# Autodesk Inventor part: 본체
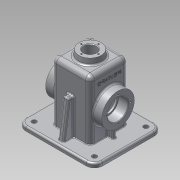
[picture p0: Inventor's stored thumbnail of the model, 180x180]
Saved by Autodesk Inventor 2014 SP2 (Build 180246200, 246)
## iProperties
Created: 2016-08
Part Number: 본체
Material: 알루미늄 6061
Document SubType Name: Modeling
Designer: user
Density: 2.71 g/cm^3
Appearance: 알루미늄 - 평지
Mass: 796.016 g
Surface Area: 911.319 cm^2
Volume: 293.733 cm^3
Author: user
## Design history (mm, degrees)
sketch "스케치1"
  geometry: L1 (-32.5, -32.5)-(32.5, -32.5); L2 (32.5, -32.5)-(32.5, 32.5); L3 (32.5, 32.5)-(-32.5, 32.5); L4 (-32.5, 32.5)-(-32.5, -32.5); L5 (-32.5, -32.5)-(32.5, 32.5); L6 (32.5, -32.5)-(-32.5, 32.5); 1 further point
  constraints: 12 end point, 2 midpoint, 2 parallel, 1 horizontal, 1 perpendicular
  dimensions: "d0" = 65 distance of L3.end L2.end; "d1" = 65 distance of L2.end L1.end
extrude "돌출1" new body sketch "스케치1" stored distance "d2" = 100; taper "d3" = 0 deg
sketch "스케치2"
  geometry: L1 (65, 57.5)-(-65, 57.5); L2 (-65, 57.5)-(-65, -57.5); L3 (-65, -57.5)-(65, -57.5); L4 (65, -57.5)-(65, 57.5); L5 (65, 57.5)-(-65, -57.5); L6 (-65, 57.5)-(65, -57.5); 1 further point
  constraints: 12 end point, 2 midpoint, 2 parallel, 1 horizontal, 1 perpendicular
  dimensions: "d4" = 130 distance of L3.end L2.end; "d5" = 115 distance of L2.end L1.end
extrude "돌출2" join sketch "스케치2" distance "d6" = 7; taper "d7" = 0 deg
sketch "스케치3"
  geometry: L1 (-65, -57.5)-(65, -57.5) reference; L2 (65, -57.5)-(65, 57.5) reference; L3 (65, 57.5)-(-65, 57.5) reference; L4 (-65, 57.5)-(-65, -57.5) reference; L5 (60, -52.5)-(-60, -52.5); L6 (-60, -52.5)-(-60, 52.5); L7 (-60, 52.5)-(60, 52.5); L8 (60, 52.5)-(60, -52.5); 1 further point
  constraints: 8 end point, 3 other
  dimensions: "d8" = 5 distance between parallel lines of L1 L5
extrude "돌출3" join sketch "스케치3" distance "d9" = 3; taper "d10" = 0 deg
fillet "모깎기1" dims "d11" = 8
fillet "모깎기2" dims "d12" = 8
sketch "스케치4"
  geometry: L1 (10, 77)-(10, -28) reference; L2 (-92, -8)-(0, -8) reference; C1 r 27.5 at (-45, 24.5); 1 further point
  constraints: 1 centre point
  dimensions: "d13" = 55 distance from line of L1 C1.centre; "d14" = 55 diameter of C1; "d15" = 32.5 distance from line of L2 C1.centre
extrude "돌출4" join sketch "스케치4" distance "d16" = 15; taper "d17" = 0 deg
sketch "스케치5"
  geometry: L1 (60, -60)-(-60, -60) reference; L2 (27.5, -60)-(27.5, 42); L3 (24.5, 45)-(-24.5, 45); L4 (-27.5, 42)-(-27.5, -60); L5 (27.5, -60)-(-27.5, -60); L6 (32.5, 7.49)-(32.5, 42) reference; L7 (-32.5, 42)-(-32.5, 7.49) reference; L8 (24.5, 50)-(-24.5, 50) reference; A1 r 3 centre (24.5, 42) between (27.5, 42) and (24.5, 45); A2 r 3 centre (-24.5, 42) between (-24.5, 45) and (-27.5, 42); 1 further point
  constraints: 8 end point, 4 perpendicular, 4 point on circle, 4 tangent, 2 centre point, 2 point on line, 1 equal radius
  dimensions: "d18" = 5 distance between parallel lines of L6 L2; "d19" = 5 distance between parallel lines of L7 L4; "d20" = 5 distance between parallel lines of L3 L8; "d21" = 3 radius of A1
extrude "돌출5" cut sketch "스케치5" stored distance "d22" = 55; taper "d23" = 0 deg
fillet "모깎기3" dims "d24" = 3
sketch "스케치7"
  geometry: L1 (32.5, 42)-(32.5, -50) reference; L2 (-57.5, -50)-(57.5, -50) reference; L3 (57.5, -50)-(57.5, -57) reference; L4 (49.5, -50)-(41.068, 10); L5 (-52.5, -60)-(52.5, -60) reference; L6 (-49.5, -50)-(-41.068, 10); L7 (-57.5, -50)-(-57.5, -57) reference; L8 (41.068, 10)-(32.5, 10); 1 further point
  constraints: 6 end point, 3 point on line, 1 perpendicular
  dimensions: "d30" = 70 distance from line of L5 L4.end; "d31" = 8 deg angle of L3 L4; "d32" = 8 distance of L2.end L4.start; "d33" = 8 deg angle of L7 L6; "d34" = 70 distance from line of L5 L6.end; "d35" = 8 distance from line of L7 L6.start
feature "리브1" sketch "스케치7" dims "d36" = 1, "d37" = 10, "d38" = 0, "d39" = 0, "d40" = 1, "d41" = 1
sketch "스케치8"
  geometry: L1 (47.5, 22.5)-(47.5, -32.5) reference; L2 (47.5, -5)-(-47.5, -5); L3 (-47.5, 22.5)-(-47.5, -32.5) reference; L4 (47.5, -5)-(47.5, 12.5); L5 (47.5, 12.5)-(30.5, 12.5); L6 (30.5, 12.5)-(30.5, 10); L7 (30.5, 10)-(-30.5, 10); L8 (-30.5, 10)-(-30.5, 12.5); L9 (-30.5, 12.5)-(-47.5, 12.5); L10 (-47.5, 12.5)-(-47.5, -5); 1 further point
  constraints: 16 end point, 5 perpendicular, 2 midpoint, 2 parallel, 2 point on line
  dimensions: "d42" = 17 distance of L4.end L5.end; "d43" = 17 distance of L8.end L9.end; "d44" = 30 diameter of L7 L2; "d45" = 35 diameter of L9 L2; "d46" = 35 diameter of L5 L2
revolve "회전1" sketch "스케치8" stored, may be unused: angle "d47" = 90 deg
sketch "스케치9"
  geometry: C1 r 27.5 at (0, 0) reference; 2 further points
  constraints: 1 horizontal alignment
  dimensions: "d48" = 21 distance of C1.centre point (-21, 0)
hole "구멍1" sketch "스케치9" at (-21, 0) diameter "d49" = 3.242; stored, may be unused: countersink angle "d53" = 90 deg, drill point angle "d55" = 118 deg; dims "d50" = 8, "d51" = 4, "d52" = 2, "d54" = 10
fillet "모깎기4" dims "d59" = 14
fillet "모깎기5" dims "d60" = 9
hole "구멍2" diameter "d63" = 8; stored, may be unused: countersink angle "d67" = 90 deg, drill point angle "d69" = 118 deg; dims "d61" = 10, "d62" = 10, "d64" = 8, "d65" = 4, "d66" = 2, "d68" = 10
hole "구멍3" diameter "d72" = 8; stored, may be unused: countersink angle "d76" = 90 deg, drill point angle "d78" = 118 deg; dims "d70" = 10, "d71" = 10, "d73" = 8, "d74" = 4, "d75" = 2, "d77" = 10
hole "구멍4" diameter "d81" = 8; stored, may be unused: countersink angle "d85" = 90 deg, drill point angle "d87" = 118 deg; dims "d79" = 10, "d80" = 10, "d82" = 8, "d83" = 4, "d84" = 2, "d86" = 10
hole "구멍5" diameter "d90" = 8; stored, may be unused: countersink angle "d94" = 90 deg, drill point angle "d96" = 118 deg; dims "d88" = 10, "d89" = 10, "d91" = 8, "d92" = 4, "d93" = 2, "d95" = 10
sketch "스케치11"
  geometry: C1 r 20 at (0, 0); 1 further point
  constraints: 1 centre point, 1 coincident
  dimensions: "d97" = 40 diameter of C1
extrude "돌출7" join sketch "스케치11" distance "d98" = 10; taper "d99" = -7 deg
hole "구멍6" diameter "d102" = 21; stored, may be unused: countersink angle "d106" = 90 deg, drill point angle "d108" = 118 deg; dims "d100" = 10, "d101" = 10, "d103" = 8, "d104" = 4, "d105" = 2, "d107" = 10
sketch "스케치12"
  geometry: A1 r 14.5 centre (0, 0) between (0, 14.5) and (0, -14.5); 3 further points
  constraints: 4 point on circle, 2 horizontal alignment, 2 vertical alignment, 1 centre point, 1 coincident
  dimensions: "d109" = 29 diameter of A1
hole "구멍7" sketch "스케치12" at (0, 14.5), (0, -14.5), (14.5, 0), (-14.5, 0) diameter "d110" = 2.459; stored, may be unused: countersink angle "d114" = 90 deg, drill point angle "d116" = 118 deg; dims "d111" = 7, "d112" = 4, "d113" = 2, "d115" = 9
node "작업 평면1"
sketch "스케치13"
  geometry: L1 (0, -8)-(92, -8) reference; L2 (-18, 5.728)-(-18, 43.272) reference; 2 further points
  constraints: 1 other
  dimensions: "d119" = 26 distance from line of point (8, 24.5) L2; "d143" = 32.5 distance from line of L1 point (8, 24.5)
feature "엠보싱1" sketch "스케치13" dims "d120" = 0.5, "d121" = 0
fillet "모깎기6" dims "d122" = 3
fillet "모깎기7" dims "d123" = 3
fillet "모깎기10" dims "d126" = 3
chamfer "모따기1" distance "d127" = 1; stored, may be unused: second distance "d128" = 2, angle "d129" = 45 deg
fillet "모깎기11" dims "d130" = 0.3
sketch "스케치14"
  geometry: L1 (32.5, 3)-(42.5, 3); L2 (42.5, 3)-(42.5, -3); L3 (42.5, -3)-(32.5, -3); L4 (27.5, -24.5)-(27.5, 24.5) reference; L5 (32.5, 24.5)-(32.5, -24.5) reference; 2 further points
  constraints: 6 end point, 2 point on line, 1 horizontal, 1 horizontal alignment, 1 midpoint, 1 parallel, 1 perpendicular
  dimensions: "d132" = 6 distance of L1.end L2.end; "d133" = 15 horizontal distance of L4.end point (42.5, 0)
extrude "돌출8" join sketch "스케치14" stored distance "d134" = 10; taper "d135" = 0 deg
fillet "모깎기12" dims "d136" = 3
fillet "모깎기13" dims "d137" = 3
fillet "모깎기14" dims "d138" = 3
fillet "모깎기15" dims "d139" = 3
fillet "모깎기17" dims "d141" = 3
fillet "모깎기18" dims "d142" = 1
node "솔리드1"
mirror "대칭1"
mirror "대칭2"
mirror "대칭4"
pattern_circular "원형 패턴1" dims angle "d57" = 360 deg
mirror "대칭5"
mirror "대칭6"
other parameters: "d117" = 49.25
